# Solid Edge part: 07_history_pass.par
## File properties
Author: edge
Template: jis part.par
Last saved by: edge
Revision: 10
Application: Solid Edge
文書内容のタイプ: 0
Accuracy: 0.990
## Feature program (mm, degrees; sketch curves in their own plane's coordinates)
sketch for "unnamed Protrusion 1" plane through (0, 0, 0) normal (1, 0, 0) x-axis (0, 1, 0)
  circle centre (0, 0) radius 40
extrude "unnamed Protrusion 1" add finite 40 along +normal
sketch for "突き出し_2" plane through (0, 0, 0) normal (1, 0, 0) x-axis (0, 1, 0)
  circle centre (0, 0) radius 30
extrude "突き出し_2" add finite 60 along +normal
chamfer "面取り_1" setback 15
sketch for "突き出し_3" plane through (0, 0, 0) normal (1, 0, 0) x-axis (0, 1, 0)
  circle centre (0, 0) radius 20
extrude "突き出し_3" add finite 70 along +normal
sketch for "突き出し_4" plane through (0, 10.1404, 10.1404) normal (1, 0, 0) x-axis (0, 1, 0)
  circle centre (-10.1404, -10.1404) radius 30
extrude "突き出し_4" add finite 15 along -normal
sketch for "突き出し_5" plane through (0, 0, 0) normal (1, 0, 0) x-axis (0, 1, 0)
  circle centre (0, 0) radius 20
extrude "突き出し_5" add finite 35 along -normal
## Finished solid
Body 1: solid body, 11 faces, 10 edges, 0 vertices.
  Faces by surface: cylinder 5, plane 5, cone 1
  Edges by curve: circle 10
Bounding box of the edges (mm): 105.000 x 80.000 x 80.000, from (-35, -40, -40) to (70, 40, 40).
Cylindrical faces by radius (mm): R20 x2, R30 x2, R40 x1
Conical faces (half-angle, radius in mm at the cone's reference point): 45 deg R30 x1
Planar faces by outward normal: +x 2, -x 3
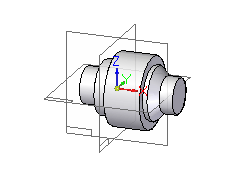
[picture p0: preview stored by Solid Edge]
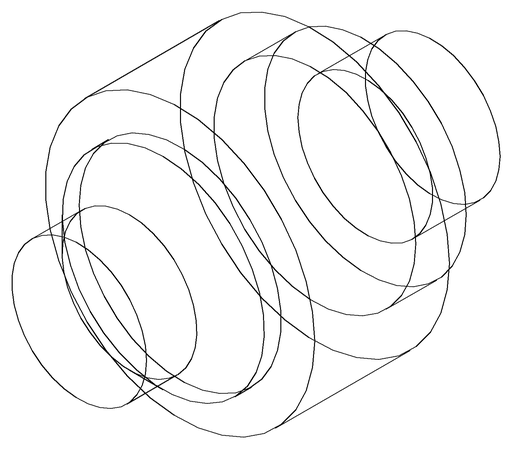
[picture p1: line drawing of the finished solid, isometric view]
